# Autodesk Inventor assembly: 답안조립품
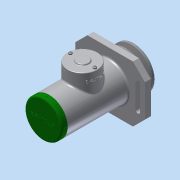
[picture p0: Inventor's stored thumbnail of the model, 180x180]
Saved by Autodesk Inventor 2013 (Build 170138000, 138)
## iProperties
Created: 2017-10
Part Number: 답안조립품
Document SubType Name: Assembly
Designer: Administrator
Author: Administrator
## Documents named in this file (19)
- C:\Users\Administrator\Desktop\471008V1017\답안조립품.iam
- C:\Users\Administrator\Desktop\471008V1017\본체.ipt
- C:\Users\Administrator\Desktop\471008V1017\베어링 15 x 35 x 11.ipt
- C:\Users\Administrator\Desktop\471008V1017\부시1.ipt
- C:\Users\Administrator\Desktop\471008V1017\축.ipt
- C:\Users\Administrator\Desktop\471008V1017\멈춤링 15 x 1.ipt
- C:\Users\Administrator\Desktop\471008V1017\멈춤링 35x1.6.ipt
- C:\Users\Administrator\Desktop\471008V1017\부시2.ipt
- C:\Users\Administrator\Desktop\471008V1017\와셔 10x21.ipt
- C:\Users\Administrator\Desktop\471008V1017\너트 M10.ipt
- C:\Users\Administrator\Desktop\471008V1017\사이드 커버.ipt
- 사이드 커버.ipt
- C:\Users\Administrator\Desktop\471008V1017\오일 실 15 25 7.ipt
- C:\Users\Administrator\Desktop\471008V1017\키 4 x 4 x 18.ipt
- C:\Users\Administrator\Desktop\471008V1017\V-벨트풀리.ipt
- C:\Users\Administrator\Desktop\471008V1017\와셔 4x16.ipt
- C:\Users\Administrator\Desktop\471008V1017\볼트 M4 x 10.ipt
- C:\Users\Administrator\Desktop\471008V1017\탑 커버.ipt
- C:\Users\Administrator\Desktop\471008V1017\십자볼트 M3 x 10.ipt
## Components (2 placed, 2 different names)
1. V-벨트풀리:1 — 각도:2
2. ISO 4017 M4 x 10:1
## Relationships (1: Angle 1)
- 각도:2 [Angle]: V-벨트풀리:1
